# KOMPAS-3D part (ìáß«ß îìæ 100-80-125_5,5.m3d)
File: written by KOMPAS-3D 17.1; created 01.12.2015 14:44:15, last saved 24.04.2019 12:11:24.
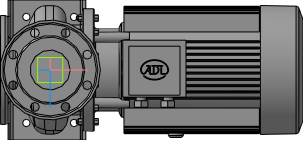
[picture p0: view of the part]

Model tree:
1. Операция без истории:2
